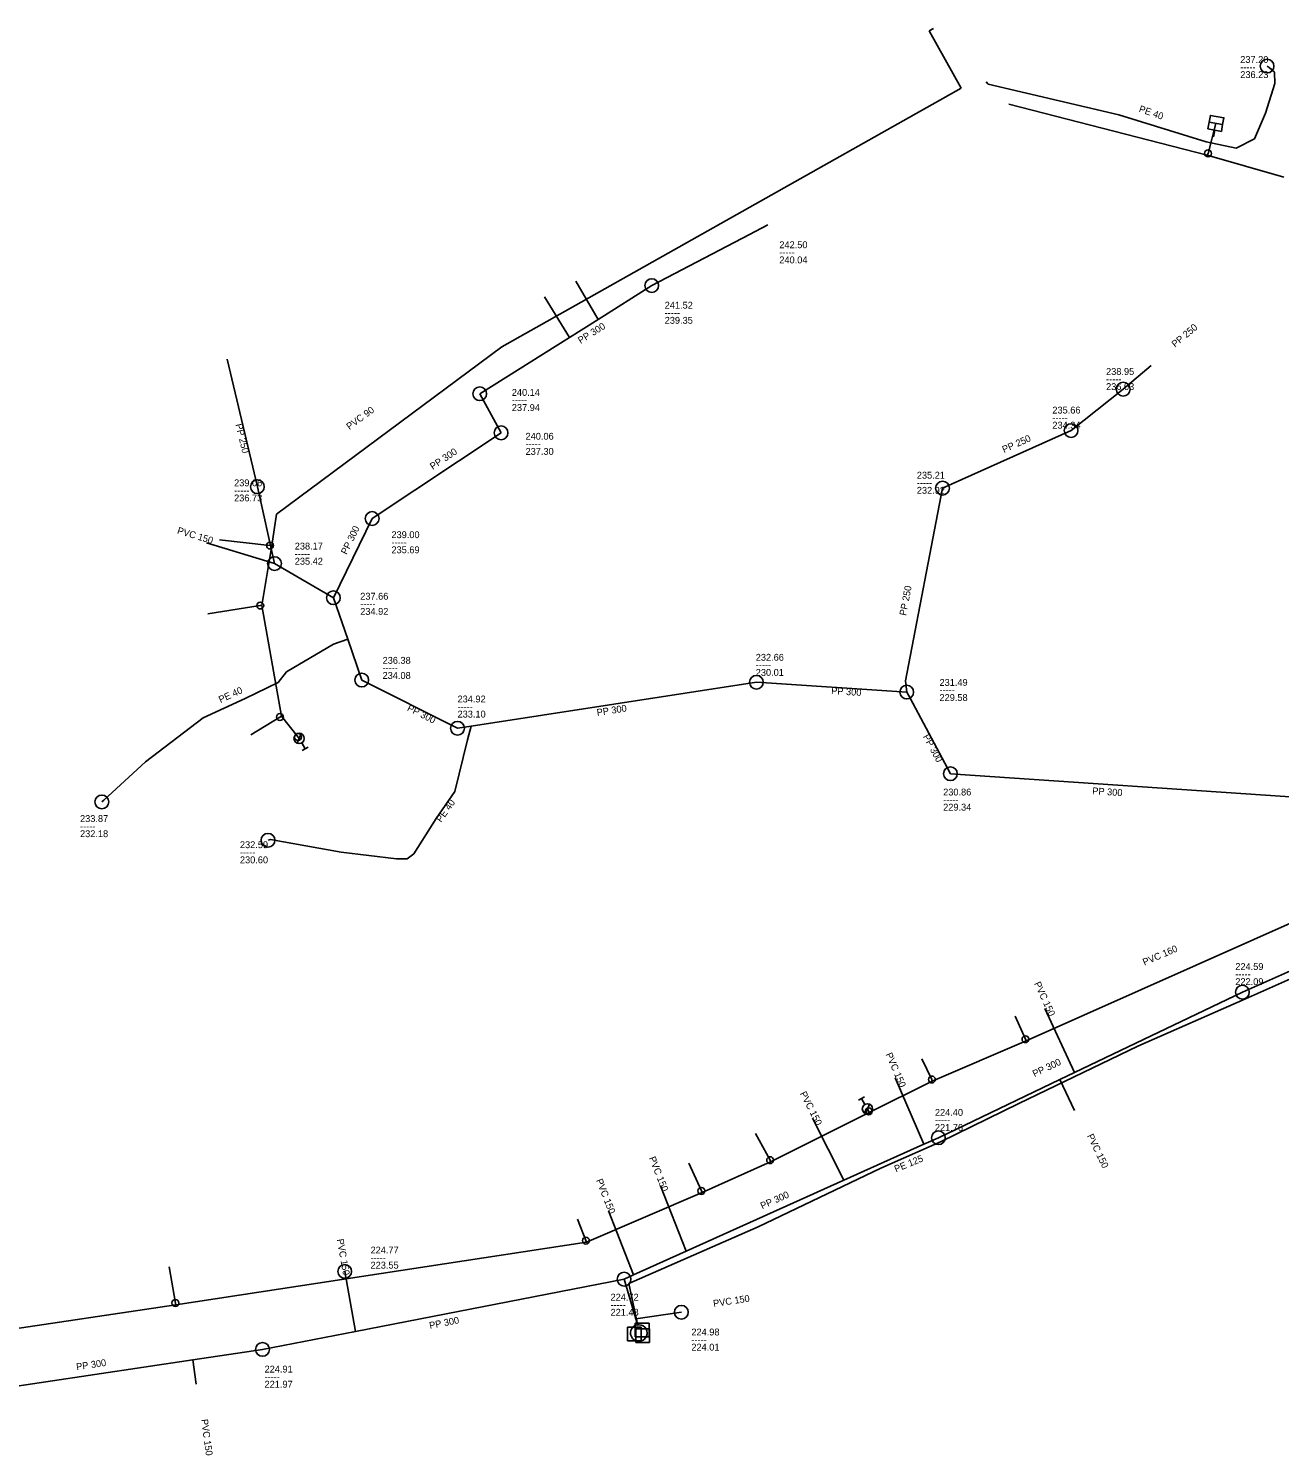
# Model space of a CAD drawing. Extents: x -771212 to -769571, y -1050452 to -1050119.
# Drawn here: x -770462.8 to -770280.9, y -1050340 to -1050132.5 of the extents above; entities that cross this region are included whole.
import ezdxf

# ---------------------------------------------------------------- set-up
doc = ezdxf.new("R2010")
doc.units = 0
doc.layers.add('Level 0', color=7, linetype='Continuous')

msp = doc.modelspace()

# ---------------------------------------------------------------- linework, layer by layer
at = {"layer": 'Level 0'}
for p, q in [((-770331.19, -1050132.54), (-770331.83, -1050132.89)), ((-770331.83, -1050132.89), (-770327.16, -1050141.19)), ((-770282.36, -1050138.19), (-770282.68, -1050137.99)), ((-770281.59, -1050138.87), (-770282.36, -1050138.19)), ((-770281.54, -1050140.52), (-770281.59, -1050138.87)), ((-770327.16, -1050141.19), (-770393.96, -1050178.83)), ((-770323.54, -1050140.28), (-770323.22, -1050140.62)), ((-770323.22, -1050140.62), (-770317.65, -1050141.95)), ((-770282.91, -1050144.86), (-770281.54, -1050140.52)), ((-770291.37, -1050150.94), (-770320.23, -1050143.52)), ((-770317.65, -1050141.95), (-770304.26, -1050145.1)), ((-770304.26, -1050145.1), (-770291.53, -1050149.02)), ((-770284.49, -1050148.58), (-770282.91, -1050144.86)), ((-770290.12, -1050146.33), (-770291.26, -1050150.7)), ((-770290.47, -1050148.3), (-770290.29, -1050147.31)), ((-770291.53, -1050149.02), (-770287.18, -1050149.92)), ((-770287.18, -1050149.92), (-770284.49, -1050148.58)), ((-770291.26, -1050150.7), (-770291.37, -1050150.94)), ((-770280.22, -1050154.16), (-770291.37, -1050150.94)), ((-770357.92, -1050162.47), (-770372.15, -1050169.92)), ((-770355.27, -1050161.08), (-770357.92, -1050162.47)), ((-770379.96, -1050174.83), (-770383.18, -1050169.29)), ((-770372.15, -1050169.92), (-770379.96, -1050174.83)), ((-770384.13, -1050177.45), (-770387.75, -1050171.53)), ((-770379.96, -1050174.83), (-770384.13, -1050177.45)), ((-770393.96, -1050178.83), (-770426.7, -1050203.15)), ((-770384.13, -1050177.45), (-770397.16, -1050185.64)), ((-770433.91, -1050180.6), (-770429.5, -1050199.16)), ((-770303.6, -1050184.98), (-770299.54, -1050181.56)), ((-770303.6, -1050184.98), (-770311.18, -1050191)), ((-770397.16, -1050185.64), (-770394.06, -1050191.33)), ((-770394.06, -1050191.33), (-770412.81, -1050203.79)), ((-770311.18, -1050191), (-770329.87, -1050199.37)), ((-770429.5, -1050199.16), (-770427, -1050210.34)), ((-770329.87, -1050199.37), (-770335.26, -1050227.37)), ((-770426.7, -1050203.15), (-770427.38, -1050207.73)), ((-770412.81, -1050203.79), (-770418.44, -1050215.3)), ((-770427, -1050210.34), (-770436.87, -1050207.34)), ((-770427.66, -1050207.72), (-770435, -1050206.89)), ((-770427.38, -1050207.73), (-770428.84, -1050216.44)), ((-770427.38, -1050207.73), (-770427.66, -1050207.72)), ((-770427, -1050210.34), (-770418.44, -1050215.3)), ((-770429.08, -1050216.44), (-770436.72, -1050217.65)), ((-770428.84, -1050216.44), (-770429.08, -1050216.44)), ((-770428.84, -1050216.44), (-770426.01, -1050232.54)), ((-770418.44, -1050215.3), (-770416.36, -1050221.35)), ((-770418.41, -1050222.04), (-770425.26, -1050226.08)), ((-770416.36, -1050221.35), (-770418.41, -1050222.04)), ((-770416.36, -1050221.35), (-770414.32, -1050227.27)), ((-770425.26, -1050226.08), (-770426.45, -1050227.63)), ((-770426.45, -1050227.63), (-770431.27, -1050229.98)), ((-770414.32, -1050227.27), (-770400.4, -1050234.29)), ((-770398.39, -1050233.98), (-770356.94, -1050227.6)), ((-770356.94, -1050227.6), (-770335.08, -1050229.03)), ((-770335.26, -1050227.37), (-770335.08, -1050229.03)), ((-770431.27, -1050229.98), (-770437.36, -1050232.77)), ((-770335.08, -1050229.03), (-770334.59, -1050229.93)), ((-770334.59, -1050229.93), (-770329.15, -1050240.09)), ((-770437.36, -1050232.77), (-770445.77, -1050239.17)), ((-770426.21, -1050232.66), (-770430.46, -1050235.22)), ((-770426.01, -1050232.54), (-770426.21, -1050232.66)), ((-770426.01, -1050232.54), (-770423.58, -1050235.56)), ((-770423.14, -1050235.07), (-770423.7, -1050236.46)), ((-770400.4, -1050234.29), (-770398.39, -1050233.98)), ((-770398.39, -1050233.98), (-770398.94, -1050235.98)), ((-770423.58, -1050235.56), (-770423.42, -1050235.76)), ((-770423.05, -1050236.41), (-770422.55, -1050237.28)), ((-770422.11, -1050237.03), (-770422.98, -1050237.53)), ((-770398.94, -1050235.98), (-770400.79, -1050243.49)), ((-770445.77, -1050239.17), (-770451.81, -1050244.73)), ((-770329.15, -1050240.09), (-770328.72, -1050240.89)), ((-770328.72, -1050240.89), (-770277.18, -1050244.39)), ((-770451.81, -1050244.73), (-770452.11, -1050245)), ((-770400.79, -1050243.49), (-770403.49, -1050247.41)), ((-770403.49, -1050247.41), (-770406.75, -1050252.53)), ((-770427.59, -1050250.44), (-770427.95, -1050250.58)), ((-770417.3, -1050252.29), (-770427.59, -1050250.44)), ((-770409.29, -1050253.28), (-770417.3, -1050252.29)), ((-770407.71, -1050253.27), (-770409.29, -1050253.28)), ((-770406.75, -1050252.53), (-770407.71, -1050253.27)), ((-770267.13, -1050257.23), (-770317.71, -1050279.72)), ((-770264.95, -1050263.2), (-770286.27, -1050272.66)), ((-770285.81, -1050273.65), (-770264.35, -1050264)), ((-770286.27, -1050272.66), (-770310.7, -1050284.36)), ((-770301.46, -1050280.51), (-770285.81, -1050273.65)), ((-770317.81, -1050279.5), (-770319.29, -1050276.15)), ((-770310.7, -1050284.36), (-770315.01, -1050275.04)), ((-770317.71, -1050279.72), (-770331.38, -1050285.6)), ((-770318.79, -1050288.84), (-770301.46, -1050280.51)), ((-770317.71, -1050279.72), (-770317.81, -1050279.5)), ((-770331.42, -1050285.36), (-770332.9, -1050282.35)), ((-770310.7, -1050284.36), (-770312.83, -1050285.38)), ((-770331.38, -1050285.6), (-770340.54, -1050290.17)), ((-770332.58, -1050294.78), (-770336.74, -1050285.12)), ((-770331.38, -1050285.6), (-770331.42, -1050285.36)), ((-770312.83, -1050285.38), (-770330.47, -1050293.83)), ((-770312.83, -1050285.38), (-770310.66, -1050289.87)), ((-770342.1, -1050288.37), (-770341.23, -1050287.87)), ((-770341.17, -1050288.99), (-770341.67, -1050288.12)), ((-770341.07, -1050290.33), (-770340.51, -1050288.94)), ((-770330.16, -1050294.43), (-770318.79, -1050288.84)), ((-770340.54, -1050290.17), (-770354.88, -1050297.33)), ((-770344.21, -1050300.01), (-770348.78, -1050291)), ((-770340.79, -1050289.64), (-770340.61, -1050290)), ((-770340.61, -1050290), (-770340.54, -1050290.17)), ((-770354.94, -1050297.09), (-770357.06, -1050293.23)), ((-770332.58, -1050294.78), (-770344.21, -1050300.01)), ((-770338.86, -1050298.24), (-770330.16, -1050294.43)), ((-770330.47, -1050293.83), (-770332.58, -1050294.78)), ((-770354.88, -1050297.33), (-770364.81, -1050301.79)), ((-770354.88, -1050297.33), (-770354.94, -1050297.09)), ((-770364.93, -1050301.57), (-770366.74, -1050297.55)), ((-770356.68, -1050306.8), (-770338.86, -1050298.24)), ((-770367.13, -1050310.32), (-770370.87, -1050300.82)), ((-770344.21, -1050300.01), (-770367.13, -1050310.32)), ((-770364.81, -1050301.79), (-770381.64, -1050309.03)), ((-770364.81, -1050301.79), (-770364.93, -1050301.57)), ((-770381.73, -1050308.79), (-770382.96, -1050305.65)), ((-770374.8, -1050313.77), (-770378.45, -1050304.48)), ((-770375.48, -1050315.03), (-770356.68, -1050306.8)), ((-770381.64, -1050309.03), (-770441.37, -1050318.11)), ((-770381.64, -1050309.03), (-770381.73, -1050308.79)), ((-770367.13, -1050310.32), (-770374.8, -1050313.77)), ((-770441.42, -1050317.86), (-770442.33, -1050312.6)), ((-770415.24, -1050321.98), (-770416.79, -1050313.27)), ((-770374.8, -1050313.77), (-770376.18, -1050314.39)), ((-770415.24, -1050321.98), (-770376.18, -1050314.39)), ((-770376.18, -1050314.39), (-770374.46, -1050320.17)), ((-770374.17, -1050321.15), (-770375.48, -1050315.03)), ((-770441.37, -1050318.11), (-770569.94, -1050337.38)), ((-770441.37, -1050318.11), (-770441.42, -1050317.86)), ((-770367.85, -1050319.2), (-770374.46, -1050320.17)), ((-770374.46, -1050320.17), (-770374.17, -1050321.15)), ((-770428.75, -1050324.6), (-770415.24, -1050321.98)), ((-770373.67, -1050321.37), (-770375.67, -1050321.37)), ((-770375.67, -1050321.37), (-770375.67, -1050323.37)), ((-770375.18, -1050321.84), (-770375.24, -1050322.15)), ((-770375.24, -1050322.15), (-770375.22, -1050322.46)), ((-770375.05, -1050321.56), (-770375.18, -1050321.84)), ((-770374.85, -1050321.33), (-770375.05, -1050321.56)), ((-770374.6, -1050321.15), (-770374.85, -1050321.33)), ((-770374.3, -1050321.04), (-770374.6, -1050321.15)), ((-770372.55, -1050320.8), (-770374.55, -1050320.8)), ((-770374.55, -1050320.8), (-770374.55, -1050322.8)), ((-770372.46, -1050321.61), (-770374.46, -1050321.61)), ((-770374.46, -1050321.61), (-770374.46, -1050323.61)), ((-770374, -1050321.01), (-770374.3, -1050321.04)), ((-770373.69, -1050321.06), (-770374, -1050321.01)), ((-770373.4, -1050321.18), (-770373.69, -1050321.06)), ((-770373.67, -1050323.37), (-770373.67, -1050321.37)), ((-770373.16, -1050321.37), (-770373.4, -1050321.18)), ((-770372.97, -1050321.62), (-770373.16, -1050321.37)), ((-770372.86, -1050321.91), (-770372.97, -1050321.62)), ((-770372.82, -1050322.22), (-770372.86, -1050321.91)), ((-770372.83, -1050322.35), (-770372.82, -1050322.22)), ((-770372.55, -1050322.8), (-770372.55, -1050320.8)), ((-770372.46, -1050323.61), (-770372.46, -1050321.61)), ((-770375.67, -1050323.37), (-770373.67, -1050323.37)), ((-770375.22, -1050322.46), (-770375.12, -1050322.75)), ((-770375.12, -1050322.75), (-770374.94, -1050323.01)), ((-770374.94, -1050323.01), (-770374.71, -1050323.22)), ((-770374.71, -1050323.22), (-770374.44, -1050323.36)), ((-770374.55, -1050322.8), (-770372.55, -1050322.8)), ((-770374.46, -1050323.61), (-770372.46, -1050323.61)), ((-770374.44, -1050323.36), (-770374.13, -1050323.43)), ((-770374.13, -1050323.43), (-770373.82, -1050323.41)), ((-770373.82, -1050323.41), (-770373.52, -1050323.32)), ((-770373.52, -1050323.32), (-770373.26, -1050323.16)), ((-770373.26, -1050323.16), (-770373.05, -1050322.93)), ((-770373.05, -1050322.93), (-770372.9, -1050322.66)), ((-770372.9, -1050322.66), (-770372.83, -1050322.35)), ((-770472.35, -1050331.14), (-770438.88, -1050326.12)), ((-770438.88, -1050326.12), (-770428.75, -1050324.6)), ((-770438.88, -1050326.12), (-770438.4, -1050329.67))]:
    msp.add_line(p, q, dxfattribs=at)
msp.add_lwpolyline([(-770291.1, -1050146.16), (-770290.93, -1050145.17), (-770288.96, -1050145.52), (-770289.14, -1050146.5)], dxfattribs=at)
msp.add_lwpolyline([(-770291.28, -1050147.14), (-770289.31, -1050147.49), (-770289.14, -1050146.5), (-770291.1, -1050146.16)], close=True, dxfattribs=at)
for centre, radius in [((-770282.68, -1050137.99), 1), ((-770291.26, -1050150.7), 0.5), ((-770372.15, -1050169.92), 1), ((-770397.16, -1050185.64), 1), ((-770303.6, -1050184.98), 1), ((-770394.06, -1050191.33), 1), ((-770311.18, -1050191), 1), ((-770429.5, -1050199.16), 1), ((-770329.87, -1050199.37), 1), ((-770412.81, -1050203.79), 1), ((-770427.66, -1050207.72), 0.5), ((-770427, -1050210.34), 1), ((-770418.44, -1050215.3), 1), ((-770429.08, -1050216.44), 0.5), ((-770414.32, -1050227.27), 1), ((-770356.94, -1050227.6), 1), ((-770335.08, -1050229.03), 1), ((-770426.21, -1050232.66), 0.5), ((-770423.42, -1050235.76), 0.75), ((-770423.58, -1050235.56), 0.5), ((-770400.4, -1050234.29), 1), ((-770328.72, -1050240.89), 1), ((-770452.11, -1050245), 1), ((-770427.95, -1050250.58), 1), ((-770286.27, -1050272.66), 1), ((-770317.81, -1050279.5), 0.5), ((-770331.42, -1050285.36), 0.5), ((-770340.79, -1050289.64), 0.75), ((-770340.61, -1050290), 0.5), ((-770330.47, -1050293.83), 1), ((-770354.94, -1050297.09), 0.5), ((-770364.93, -1050301.57), 0.5), ((-770381.73, -1050308.79), 0.5), ((-770416.79, -1050313.27), 1), ((-770376.18, -1050314.39), 1), ((-770441.42, -1050317.86), 0.5), ((-770367.85, -1050319.2), 1), ((-770428.75, -1050324.6), 1)]:
    msp.add_circle(centre, radius, dxfattribs=at)

# ---------------------------------------------------------------- texts
for s, p in [('237.20', (-770286.58, -1050137.54)), ('-----', (-770286.58, -1050138.64)), ('236.23', (-770286.58, -1050139.74)), ('242.50', (-770353.6, -1050164.48)), ('-----', (-770353.6, -1050165.58)), ('240.04', (-770353.6, -1050166.68)), ('241.52', (-770370.27, -1050173.27)), ('-----', (-770370.27, -1050174.37)), ('239.35', (-770370.27, -1050175.47)), ('238.95', (-770306.09, -1050182.91)), ('240.14', (-770392.5, -1050185.95)), ('-----', (-770306.09, -1050184.01)), ('236.03', (-770306.09, -1050185.11)), ('-----', (-770392.5, -1050187.05)), ('237.94', (-770392.5, -1050188.15)), ('-----', (-770313.9, -1050189.62)), ('235.66', (-770313.9, -1050188.52)), ('240.06', (-770390.5, -1050192.33)), ('234.34', (-770313.9, -1050190.72)), ('-----', (-770390.5, -1050193.43)), ('237.30', (-770390.5, -1050194.53)), ('235.21', (-770333.61, -1050197.99)), ('-----', (-770432.88, -1050200.2)), ('239.06', (-770432.88, -1050199.1)), ('-----', (-770333.61, -1050199.09)), ('232.92', (-770333.61, -1050200.19)), ('236.73', (-770432.88, -1050201.3)), ('239.00', (-770410, -1050206.64)), ('238.17', (-770424.06, -1050208.3)), ('-----', (-770410, -1050207.74)), ('235.69', (-770410, -1050208.84)), ('-----', (-770424.06, -1050209.4)), ('235.42', (-770424.06, -1050210.5)), ('-----', (-770414.54, -1050216.69)), ('237.66', (-770414.54, -1050215.59)), ('234.92', (-770414.54, -1050217.79)), ('236.38', (-770411.29, -1050224.91)), ('232.66', (-770357.03, -1050224.47)), ('-----', (-770411.29, -1050226.01)), ('234.08', (-770411.29, -1050227.11)), ('-----', (-770357.03, -1050225.57)), ('230.01', (-770357.03, -1050226.67)), ('-----', (-770330.31, -1050229.22)), ('231.49', (-770330.31, -1050228.12)), ('234.92', (-770400.39, -1050230.53)), ('229.58', (-770330.31, -1050230.32)), ('-----', (-770400.39, -1050231.63)), ('233.10', (-770400.39, -1050232.73)), ('230.86', (-770329.78, -1050244.06)), ('-----', (-770329.78, -1050245.16)), ('229.34', (-770329.78, -1050246.26)), ('233.87', (-770455.28, -1050247.92)), ('-----', (-770455.28, -1050249.02)), ('232.18', (-770455.28, -1050250.12)), ('232.59', (-770432.03, -1050251.72)), ('-----', (-770432.03, -1050252.82)), ('230.60', (-770432.03, -1050253.92)), ('-----', (-770287.3, -1050270.53)), ('224.59', (-770287.3, -1050269.43)), ('222.09', (-770287.3, -1050271.63)), ('224.40', (-770330.98, -1050290.64)), ('-----', (-770330.98, -1050291.74)), ('221.76', (-770330.98, -1050292.84)), ('224.77', (-770413.04, -1050310.66)), ('-----', (-770413.04, -1050311.76)), ('223.55', (-770413.04, -1050312.86)), ('224.72', (-770378.14, -1050317.51)), ('-----', (-770378.14, -1050318.61)), ('221.48', (-770378.14, -1050319.71)), ('224.98', (-770366.39, -1050322.58)), ('-----', (-770366.39, -1050323.68)), ('224.01', (-770366.39, -1050324.78)), ('224.91', (-770428.45, -1050327.97)), ('-----', (-770428.45, -1050329.07)), ('221.97', (-770428.45, -1050330.17))]:
    msp.add_text(s, height=1, dxfattribs=at).set_placement(p)
for s, rotation, p in [('PE 40', 340.76, (-770301.4, -1050144.62)), ('PP 300', 32.141, (-770382.5, -1050178.41)), ('PP 250', 40.11, (-770296.05, -1050178.97)), ('PVC 90', 36.261, (-770416.11, -1050190.94)), ('PP 250', 283.366, (-770432.68, -1050190.11)), ('PP 300', 33.605, (-770403.99, -1050196.73)), ('PP 250', 24.124, (-770320.93, -1050194.27)), ('PVC 150', 343.093, (-770441.23, -1050205.95)), ('PP 300', 63.935, (-770416.52, -1050209.11)), ('PP 250', 79.104, (-770335.18, -1050217.97)), ('PE 40', 24.614, (-770434.85, -1050230.63)), ('PP 300', 356.257, (-770346.08, -1050229.31)), ('PP 300', 333.238, (-770407.81, -1050231.67)), ('PP 300', 8.768, (-770380.07, -1050232.5)), ('PP 300', 298.166, (-770332.75, -1050235.48)), ('PP 300', 356.115, (-770308.12, -1050243.87)), ('PE 40', 54.596, (-770402.78, -1050248.05)), ('PVC 160', 23.274, (-770300.51, -1050268.81)), ('PVC 150', 294.818, (-770316.58, -1050271.41)), ('PVC 150', 293.299, (-770338.17, -1050281.7)), ('PP 300', 25.589, (-770316.49, -1050285.04)), ('PVC 150', 296.895, (-770350.64, -1050287.39)), ('PVC 150', 295.794, (-770308.89, -1050293.55)), ('PVC 150', 291.489, (-770372.58, -1050296.78)), ('PE 125', 22.348, (-770336.64, -1050298.88)), ('PVC 150', 291.45, (-770380.28, -1050300.02)), ('PP 300', 24.219, (-770356.08, -1050304.25)), ('PVC 150', 280.091, (-770417.95, -1050308.62)), ('PVC 150', 8.348, (-770363.15, -1050318.43)), ('PP 300', 10.996, (-770404.4, -1050321.64)), ('PP 300', 8.53, (-770455.76, -1050327.64)), ('PVC 150', 277.7, (-770437.68, -1050334.81))]:
    msp.add_text(s, height=1, rotation=rotation, dxfattribs=at).set_placement(p)

doc.saveas('drawing.dxf')
